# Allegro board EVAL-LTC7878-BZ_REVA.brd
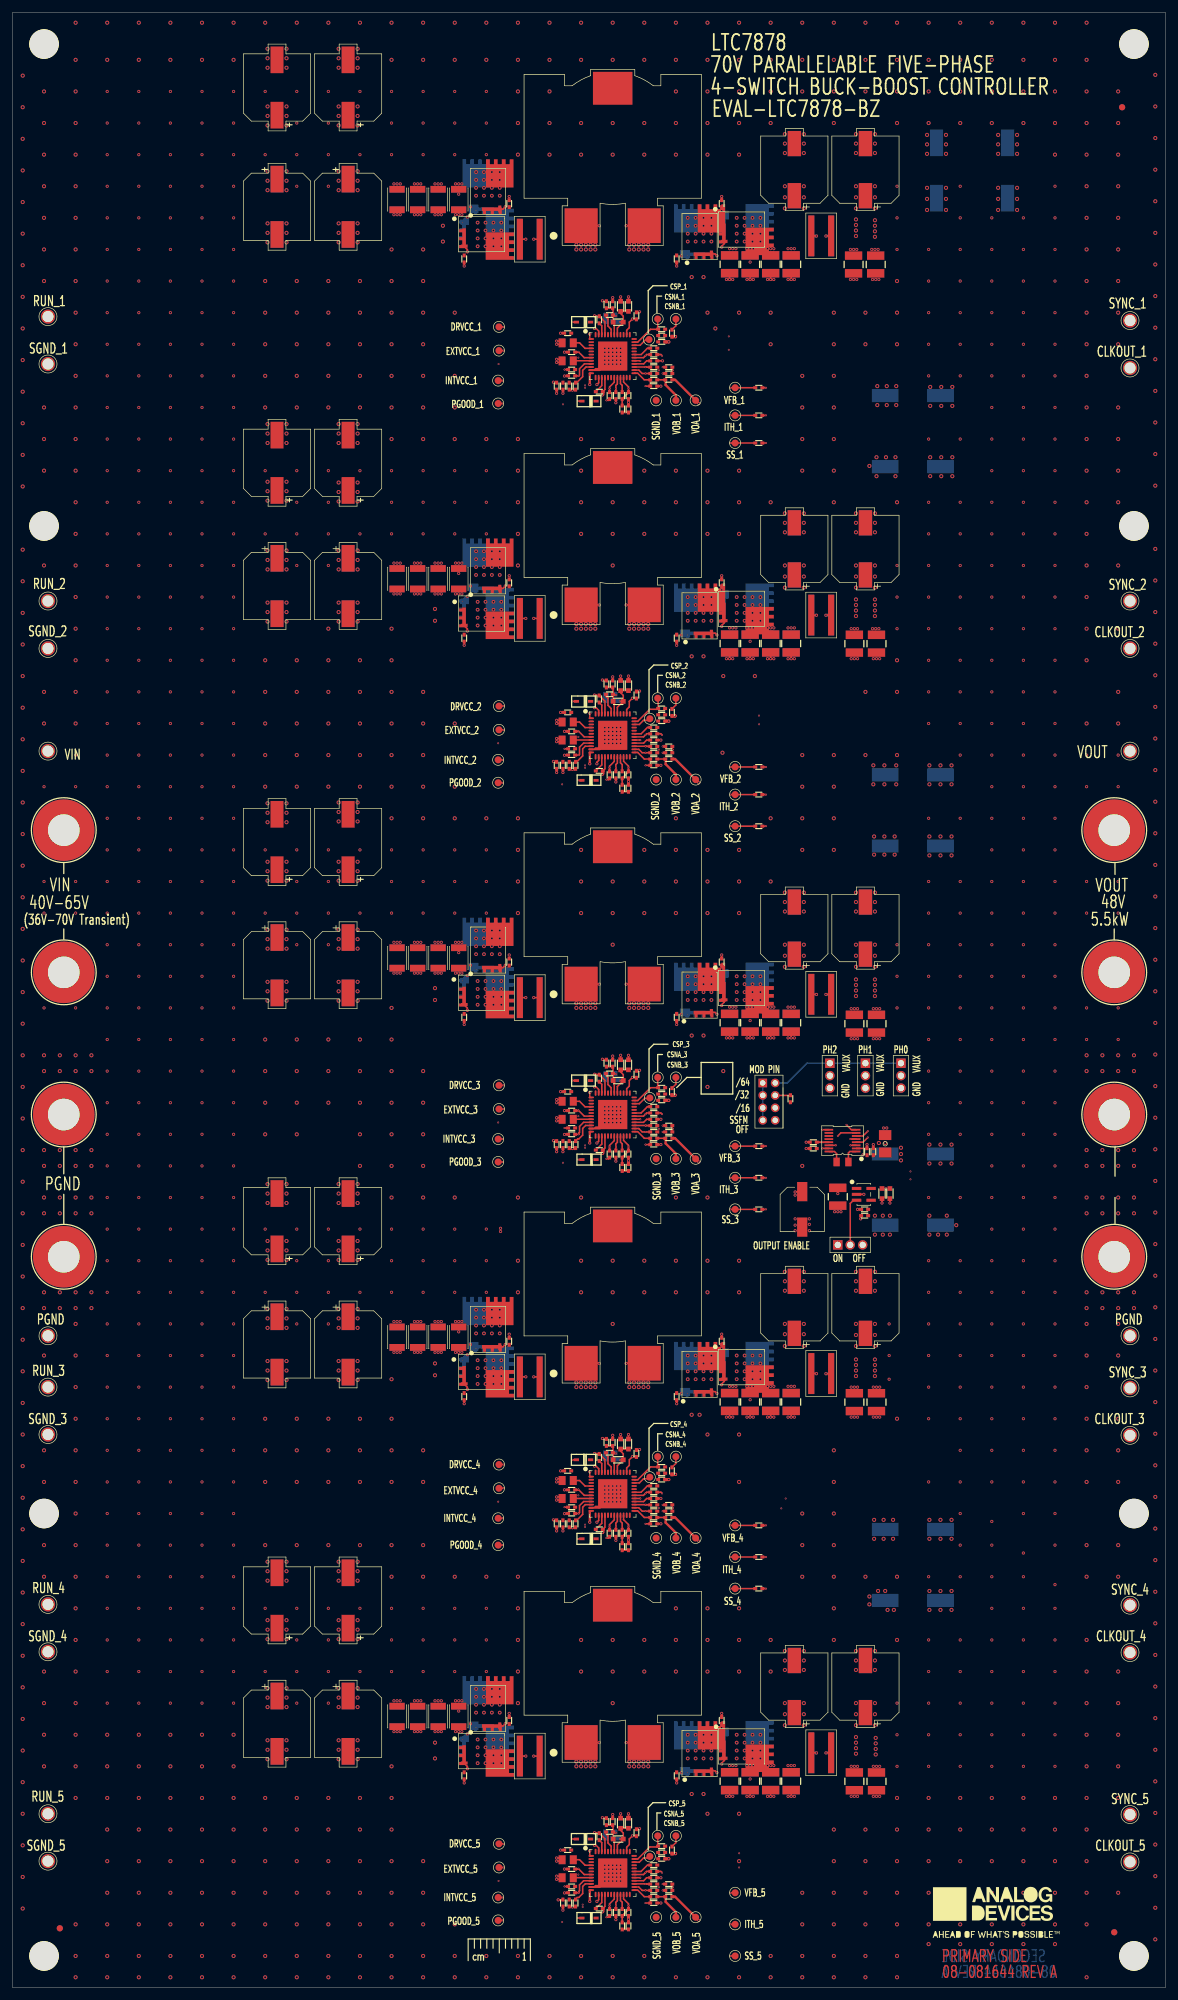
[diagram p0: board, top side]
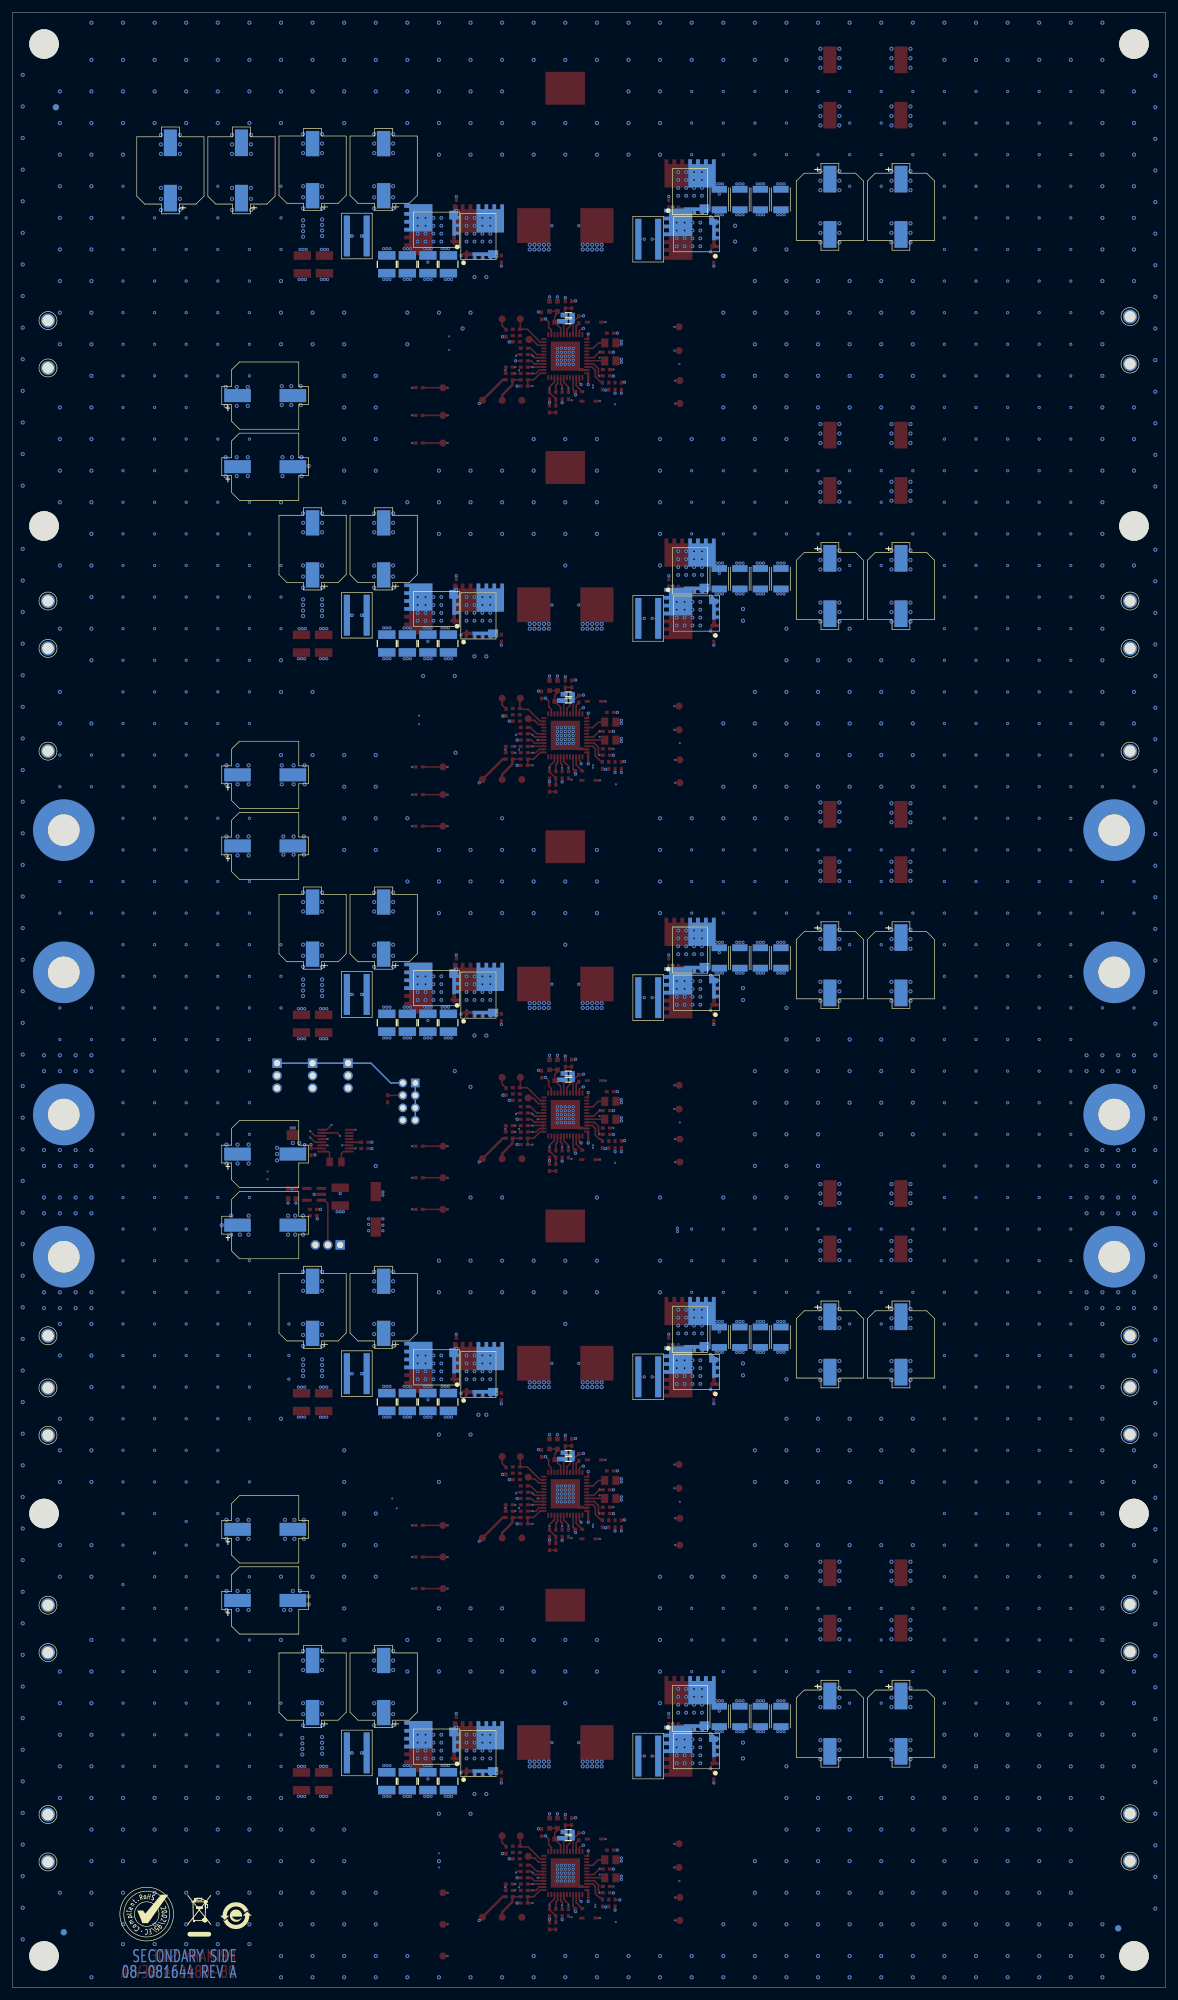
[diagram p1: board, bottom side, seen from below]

Outline 185.42 x 317.5 mm; copper layers: TOP, LAYER_2, LAYER_3, LAYER_4, LAYER_5, LAYER_6, LAYER_7, BOTTOM. Coordinates in mm from the lower left corner of the outline.
Outline path: 0,317.5 0,0 185.42,0 185.42,317.5 0,317.5

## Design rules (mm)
constraint set DEFAULT: min track width 0.254

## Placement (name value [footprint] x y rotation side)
C1  33uF  [CPLSMSQ406H413]  42.55 286.26 270 top
C2  33uF  [CPLSMSQ406H413]  53.98 286.26 270 top
C3  4.7uF  [C1210H87]  61.85 287.43 270 top
C4  4.7uF  [C1210H87]  61.85 287.43 270 bottom
C5  4.7uF  [C1210H87]  65.15 287.43 270 top
C6  4.7uF  [C1210H87]  65.15 287.43 270 bottom
C7  4.7uF  [C1210H87]  68.45 287.43 270 top
C8  4.7uF  [C1210H87]  68.45 287.43 270 bottom
C9  4.7uF  [C1210H87]  71.75 287.43 270 top
C10  4.7uF  [C1210H87]  71.75 287.43 270 bottom
C11  0.1UF  [C0402]  97.03 255.91 270 top
C12  1UF  [C0805H55]  89.28 264.39 180 top
C13  TBD0402  [C0402]  90.55 257.43 270 top
C14  100PF  [C0402]  99.06 255.91 270 top
C15  0.01uF  [C0402]  99.06 253.75 90 top
C16  1uF  [C0402]  94.36 268.1 90 top
C17  TBD0402  [C0402]  96.01 268.86 0 top
C18  6800pF  [C0603]  97.41 267.72 0 top
C19  1uF  [C0402]  94.36 256.54 180 top
C20  1UF  [C0805H55]  89.28 261.49 180 top
C21  4.7uF  [C0402]  89.92 259.08 180 top
C22  TBD0402  [C0402]  104.39 265.56 0 top
C23  4.7uF  [C0402]  89.92 262.89 180 top
C24  10UF  [C1210H110]  115.32 277.01 270 bottom
C25  10UF  [C1210H110]  118.62 277.01 270 bottom
C26  10UF  [C1210H110]  121.92 277.01 270 bottom
C27  10UF  [C1210H110]  125.22 277.01 270 top
C28  10UF  [C1210H110]  115.32 277.01 270 top
C29  10UF  [C1210H110]  118.62 277.01 270 top
C30  10UF  [C1210H110]  121.92 277.01 270 top
C31  10UF  [C1210H110]  125.22 277.01 270 bottom
C32  47UF  [CPLSMSQ406H433]  137.16 292.23 90 top
C33  47UF  [CPLSMSQ406H433]  125.73 292.23 90 top
C34  33uF  [CPLSMSQ406H413]  42.55 225.3 270 top
C35  33uF  [CPLSMSQ406H413]  53.98 225.3 270 top
C36  4.7uF  [C1210H87]  61.85 226.47 270 top
C37  4.7uF  [C1210H87]  61.85 226.47 270 bottom
C38  4.7uF  [C1210H87]  65.15 226.47 270 top
C39  4.7uF  [C1210H87]  65.15 226.47 270 bottom
C40  4.7uF  [C1210H87]  68.45 226.47 270 top
C41  4.7uF  [C1210H87]  68.45 226.47 270 bottom
C42  4.7uF  [C1210H87]  71.75 226.47 270 top
C43  4.7uF  [C1210H87]  71.75 226.47 270 bottom
C44  0.1UF  [C0402]  97.03 194.94 270 top
C45  1UF  [C0805H55]  89.28 203.43 180 top
C46  TBD0402  [C0402]  90.55 196.47 270 top
C47  100PF  [C0402]  99.06 194.94 270 top
C48  0.01uF  [C0402]  99.06 192.79 90 top
C49  1uF  [C0402]  94.36 207.14 90 top
C50  TBD0402  [C0402]  96.01 207.9 0 top
C51  6800pF  [C0603]  97.41 206.76 0 top
C52  1uF  [C0402]  94.36 195.58 180 top
C53  1UF  [C0805H55]  89.28 200.53 180 top
C54  4.7uF  [C0402]  89.92 198.12 180 top
C55  TBD0402  [C0402]  104.39 204.6 0 top
C56  4.7uF  [C0402]  89.92 201.93 180 top
C57  10UF  [C1210H110]  125.22 216.05 270 top
C58  10UF  [C1210H110]  118.62 216.05 270 top
C59  10UF  [C1210H110]  125.22 216.05 270 bottom
C60  10UF  [C1210H110]  121.92 216.05 270 top
C61  10UF  [C1210H110]  118.62 216.05 270 bottom
C62  10UF  [C1210H110]  121.92 216.05 270 bottom
C63  10UF  [C1210H110]  115.32 216.05 270 top
C64  10UF  [C1210H110]  115.32 216.05 270 bottom
C65  47UF  [CPLSMSQ406H433]  137.16 231.27 90 top
C66  47UF  [CPLSMSQ406H433]  125.73 231.27 90 top
C67  33uF  [CPLSMSQ406H413]  42.55 164.34 270 top
C68  33uF  [CPLSMSQ406H413]  53.98 164.34 270 top
C69  4.7uF  [C1210H87]  61.85 165.51 270 top
C70  4.7uF  [C1210H87]  61.85 165.51 270 bottom
C71  4.7uF  [C1210H87]  65.15 165.51 270 top
C72  4.7uF  [C1210H87]  65.15 165.51 270 bottom
C73  4.7uF  [C1210H87]  68.45 165.51 270 top
C74  4.7uF  [C1210H87]  68.45 165.51 270 bottom
C75  4.7uF  [C1210H87]  71.75 165.51 270 top
C76  4.7uF  [C1210H87]  71.75 165.51 270 bottom
C77  0.1UF  [C0402]  97.03 133.99 270 top
C78  1UF  [C0805H55]  89.28 142.47 180 top
C79  TBD0402  [C0402]  90.55 135.51 270 top
C80  100PF  [C0402]  99.06 133.99 270 top
C81  0.01uF  [C0402]  99.06 131.83 90 top
C82  1uF  [C0402]  94.36 146.18 90 top
C83  TBD0402  [C0402]  96.01 146.94 0 top
C84  6800pF  [C0603]  97.41 145.8 0 top
C85  1uF  [C0402]  94.36 134.62 180 top
C86  1UF  [C0805H55]  89.28 139.57 180 top
C87  4.7uF  [C0402]  89.92 137.16 180 top
C88  TBD0402  [C0402]  104.39 143.64 0 top
C89  4.7uF  [C0402]  89.92 140.97 180 top
C90  10UF  [C1210H110]  125.22 155.09 270 bottom
C91  10UF  [C1210H110]  125.22 155.09 270 top
C92  10UF  [C1210H110]  121.92 155.09 270 bottom
C93  10UF  [C1210H110]  118.62 155.09 270 bottom
C94  10UF  [C1210H110]  121.92 155.09 270 top
C95  10UF  [C1210H110]  118.62 155.09 270 top
C96  10UF  [C1210H110]  115.32 155.09 270 bottom
C97  10UF  [C1210H110]  115.32 155.09 270 top
C98  47UF  [CPLSMSQ406H433]  137.16 170.31 90 top
C99  47UF  [CPLSMSQ406H433]  125.73 170.31 90 top
C100  33uF  [CPLSMSQ406H413]  42.55 103.38 270 top
C101  33uF  [CPLSMSQ406H413]  53.98 103.38 270 top
C102  4.7uF  [C1210H87]  61.85 104.55 270 top
C103  4.7uF  [C1210H87]  61.85 104.55 270 bottom
C104  4.7uF  [C1210H87]  65.15 104.55 270 top
C105  4.7uF  [C1210H87]  65.15 104.55 270 bottom
C106  4.7uF  [C1210H87]  68.45 104.55 270 top
C107  4.7uF  [C1210H87]  68.45 104.55 270 bottom
C108  4.7uF  [C1210H87]  71.75 104.55 270 top
C109  4.7uF  [C1210H87]  71.75 104.55 270 bottom
C110  0.1UF  [C0402]  97.03 73.03 270 top
C111  1UF  [C0805H55]  89.28 81.51 180 top
C112  TBD0402  [C0402]  90.55 74.55 270 top
C113  100PF  [C0402]  99.06 73.03 270 top
C114  0.01uF  [C0402]  99.06 70.87 90 top
C115  1uF  [C0402]  94.36 85.22 90 top
C116  TBD0402  [C0402]  96.01 85.98 0 top
C117  6800pF  [C0603]  97.41 84.84 0 top
C118  1uF  [C0402]  94.36 73.66 180 top
C119  1UF  [C0805H55]  89.28 78.61 180 top
C120  4.7uF  [C0402]  89.92 76.2 180 top
C121  TBD0402  [C0402]  104.39 82.68 0 top
C122  4.7uF  [C0402]  89.92 80.01 180 top
C123  10UF  [C1210H110]  125.22 94.13 270 bottom
C124  10UF  [C1210H110]  125.22 94.13 270 top
C125  10UF  [C1210H110]  121.92 94.13 270 bottom
C126  10UF  [C1210H110]  118.62 94.13 270 bottom
C127  10UF  [C1210H110]  121.92 94.13 270 top
C128  10UF  [C1210H110]  118.62 94.13 270 top
C129  10UF  [C1210H110]  115.32 94.13 270 bottom
C130  10UF  [C1210H110]  115.32 94.13 270 top
C131  47UF  [CPLSMSQ406H433]  137.16 109.35 90 top
C132  47UF  [CPLSMSQ406H433]  125.73 109.35 90 top
C133  33uF  [CPLSMSQ406H413]  42.55 42.42 270 top
C134  33uF  [CPLSMSQ406H413]  53.98 42.42 270 top
C135  4.7uF  [C1210H87]  61.85 43.59 270 top
C136  4.7uF  [C1210H87]  61.85 43.59 270 bottom
C137  4.7uF  [C1210H87]  65.15 43.59 270 top
C138  4.7uF  [C1210H87]  65.15 43.59 270 bottom
C139  4.7uF  [C1210H87]  68.45 43.59 270 top
C140  4.7uF  [C1210H87]  68.45 43.59 270 bottom
C141  4.7uF  [C1210H87]  71.75 43.59 270 top
C142  4.7uF  [C1210H87]  71.75 43.59 270 bottom
C143  0.1UF  [C0402]  97.03 12.06 270 top
C144  1UF  [C0805H55]  89.28 20.55 180 top
C145  TBD0402  [C0402]  90.55 13.59 270 top
C146  100PF  [C0402]  99.06 12.06 270 top
C147  0.01uF  [C0402]  99.06 9.91 90 top
C148  1uF  [C0402]  94.36 24.26 90 top
C149  TBD0402  [C0402]  96.01 25.02 0 top
C150  6800pF  [C0603]  97.41 23.88 0 top
C151  1uF  [C0402]  94.36 12.7 180 top
C152  1UF  [C0805H55]  89.28 17.65 180 top
C153  4.7uF  [C0402]  89.92 15.24 180 top
C154  TBD0402  [C0402]  104.39 21.72 0 top
C155  4.7uF  [C0402]  89.92 19.05 180 top
C156  10UF  [C1210H110]  125.22 33.17 270 bottom
C157  10UF  [C1210H110]  125.22 33.17 270 top
C158  10UF  [C1210H110]  121.92 33.17 270 bottom
C159  10UF  [C1210H110]  118.62 33.17 270 bottom
C160  10UF  [C1210H110]  121.92 33.17 270 top
C161  10UF  [C1210H110]  118.62 33.17 270 top
C162  10UF  [C1210H110]  115.32 33.17 270 bottom
C163  10UF  [C1210H110]  115.32 33.17 270 top
C164  47UF  [CPLSMSQ406H433]  137.16 48.39 90 top
C165  47UF  [CPLSMSQ406H433]  125.73 48.39 90 top
C166  10UF  [CPLSMSQ260H315]  127 125.09 270 top
C167  1UF  [C1210H110]  132.72 127.13 270 top
C168  10UF  [C1206H71]  140.34 135.64 270 top
C169  0.1uF  [C0402]  138.43 134.37 270 top
C170  0.1uF  [C0402]  137.41 134.37 270 top
C171  0.47UF  [C0603]  139.83 127.64 270 top
C172  0.47UF  [C0603]  141.1 127.64 270 top
C173  0.1uF  [C0402]  128.78 135.89 180 top
C174  0.1uF  [C0402]  128.78 134.87 180 top
C175  1000pF  [C0402]  125.09 142.88 270 top
C176  33uF  [CPLSMSQ406H413]  42.55 286.26 270 bottom
C177  33uF  [CPLSMSQ406H413]  53.98 286.26 270 bottom
C178  47UF  [CPLSMSQ406H433]  137.16 292.23 90 bottom
C179  47UF  [CPLSMSQ406H433]  125.73 292.23 90 bottom
C180  33uF  [CPLSMSQ406H413]  42.55 225.3 270 bottom
C181  33uF  [CPLSMSQ406H413]  53.98 225.3 270 bottom
C182  47UF  [CPLSMSQ406H433]  137.16 231.27 90 bottom
C183  47UF  [CPLSMSQ406H433]  125.73 231.27 90 bottom
C184  33uF  [CPLSMSQ406H413]  42.55 164.34 270 bottom
C185  33uF  [CPLSMSQ406H413]  53.98 164.34 270 bottom
C186  47UF  [CPLSMSQ406H433]  137.16 170.31 90 bottom
C187  47UF  [CPLSMSQ406H433]  125.73 170.31 90 bottom
C188  33uF  [CPLSMSQ406H413]  42.55 103.38 270 bottom
C189  33uF  [CPLSMSQ406H413]  53.98 103.38 270 bottom
C190  47UF  [CPLSMSQ406H433]  137.16 109.35 90 bottom
C191  47UF  [CPLSMSQ406H433]  125.73 109.35 90 bottom
C192  33uF  [CPLSMSQ406H413]  42.55 42.42 270 bottom
C193  33uF  [CPLSMSQ406H413]  53.98 42.42 270 bottom
C194  47UF  [CPLSMSQ406H433]  137.16 48.39 90 bottom
C195  47UF  [CPLSMSQ406H433]  125.73 48.39 90 bottom
C196  10UF  [C1210H110]  135.25 276.99 270 top
C197  10UF  [C1210H110]  138.81 276.99 270 top
C198  10UF  [C1210H110]  138.94 216.03 270 top
C199  10UF  [C1210H110]  135.38 216.03 270 top
C200  10UF  [C1210H110]  135.38 154.94 270 top
C201  10UF  [C1210H110]  138.94 154.94 270 top
C202  10UF  [C1210H110]  135.38 94.11 270 top
C203  10UF  [C1210H110]  138.94 94.11 270 top
C204  10UF  [C1210H110]  135.38 33.15 270 top
C205  10UF  [C1210H110]  138.94 33.15 270 top
C206  33uF  [CPLSMSQ406H413]  42.55 305.44 90 top
C207  33uF  [CPLSMSQ406H413]  53.98 305.44 90 top
C208  33uF  [CPLSMSQ406H413]  148.59 292.1 90 bottom
C209  33uF  [CPLSMSQ406H413]  160.02 292.1 90 bottom
C210  33uF  [CPLSMSQ406H413]  42.55 245.11 90 top
C211  33uF  [CPLSMSQ406H413]  53.98 245.11 90 top
C212  33uF  [CPLSMSQ406H413]  144.78 244.47 180 bottom
C213  33uF  [CPLSMSQ406H413]  144.78 255.91 180 bottom
C214  33uF  [CPLSMSQ406H413]  42.55 184.15 90 top
C215  33uF  [CPLSMSQ406H413]  53.98 184.15 90 top
C216  33uF  [CPLSMSQ406H413]  144.78 183.51 180 bottom
C217  33uF  [CPLSMSQ406H413]  144.78 194.94 180 bottom
C218  33uF  [CPLSMSQ406H413]  42.55 123.19 90 top
C219  33uF  [CPLSMSQ406H413]  53.98 123.19 90 top
C220  33uF  [CPLSMSQ406H413]  144.78 133.99 180 bottom
C221  33uF  [CPLSMSQ406H413]  144.78 122.56 180 bottom
C222  33uF  [CPLSMSQ406H413]  42.55 62.23 90 top
C223  33uF  [CPLSMSQ406H413]  53.98 62.23 90 top
C224  33uF  [CPLSMSQ406H413]  144.78 62.23 180 bottom
C225  33uF  [CPLSMSQ406H413]  144.78 73.66 180 bottom
D1  BAT46WJ,115  [SOD323F]  91.82 267.72 180 top
D2  BAT46WJ,115  [SOD323F]  92.71 255.02 180 top
D3  BAT46WJ,115  [SOD323F]  91.82 206.76 180 top
D4  BAT46WJ,115  [SOD323F]  92.71 194.06 180 top
D5  BAT46WJ,115  [SOD323F]  91.82 145.8 180 top
D6  BAT46WJ,115  [SOD323F]  92.71 133.1 180 top
D7  BAT46WJ,115  [SOD323F]  91.82 84.84 180 top
D8  BAT46WJ,115  [SOD323F]  92.71 72.14 180 top
D9  BAT46WJ,115  [SOD323F]  91.82 23.88 180 top
D10  BAT46WJ,115  [SOD323F]  92.71 11.18 180 top
J1  CKFH1032-10  [CNCFCKFH1032-10]  8.26 163.19 0 top
J2  CKFH1032-10  [CNCFCKFH1032-10]  8.26 140.34 0 top
J3  CKFH1032-10  [CNCFCKFH1032-10]  177.16 163.19 0 top
J4  CKFH1032-10  [CNCFCKFH1032-10]  177.16 140.34 0 top
J5  CKFH1032-10  [CNCFCKFH1032-10]  8.26 186.06 0 top
J6  CKFH1032-10  [CNCFCKFH1032-10]  8.26 117.47 0 top
J7  CKFH1032-10  [CNCFCKFH1032-10]  177.16 186.06 0 top
J8  CKFH1032-10  [CNCFCKFH1032-10]  177.16 117.47 0 top
JP1  TMM-103-02-L-S  [CNTHMHDR1X3L236W78H215]  142.88 148.59 270 top
JP2  TMM-103-02-L-S  [CNTHMHDR1X3L236W78H215]  137.16 148.59 270 top
JP3  TMM-103-02-L-S  [CNTHMHDR1X3L236W78H215]  131.44 148.59 270 top
JP4  TMM-103-02-L-S  [CNTHMHDR1X3L236W78H215]  132.72 119.38 0 top
JP5  62000821121  [CNTHMHDR2X4L315W157H248]  120.65 145.41 270 top
L1  10UH  [LSML1102W764H728]  96.52 294.79 0 top
L2  10UH  [LSML1102W764H728]  96.52 233.83 0 top
L3  10UH  [LSML1102W764H728]  96.52 172.87 0 top
L4  10UH  [LSML1102W764H728]  96.52 111.91 0 top
L5  10UH  [LSML1102W764H728]  96.52 50.95 0 top
M1  ISC022N10NM6ATMA1  [SON8_FL]  76.45 288.7 0 top
M2  ISC022N10NM6ATMA1  [SON8_FL]  75.44 281.84 270 top
M3  ISC022N10NM6ATMA1  [SON8_FL]  110.49 281.46 0 top
M4  ISC022N10NM6ATMA1  [SON8_FL]  117.22 282.6 270 top
M5  ISC022N10NM6ATMA1  [SON8_FL]  76.45 288.7 180 bottom
M6  ISC022N10NM6ATMA1  [SON8_FL]  75.44 281.84 90 bottom
M7  ISC022N10NM6ATMA1  [SON8_FL]  110.49 281.46 180 bottom
M8  ISC022N10NM6ATMA1  [SON8_FL]  117.22 282.57 90 bottom
M9  ISC022N10NM6ATMA1  [SON8_FL]  76.45 227.74 0 top
M10  ISC022N10NM6ATMA1  [SON8_FL]  75.44 220.88 270 top
M11  ISC022N10NM6ATMA1  [SON8_FL]  110.49 220.5 0 top
M12  ISC022N10NM6ATMA1  [SON8_FL]  117.22 221.64 270 top
M13  ISC022N10NM6ATMA1  [SON8_FL]  76.45 227.74 180 bottom
M14  ISC022N10NM6ATMA1  [SON8_FL]  75.44 220.88 90 bottom
M15  ISC022N10NM6ATMA1  [SON8_FL]  110.49 220.5 180 bottom
M16  ISC022N10NM6ATMA1  [SON8_FL]  117.22 221.62 90 bottom
M17  ISC022N10NM6ATMA1  [SON8_FL]  76.45 166.78 0 top
M18  ISC022N10NM6ATMA1  [SON8_FL]  75.44 159.92 270 top
M19  ISC022N10NM6ATMA1  [SON8_FL]  110.49 159.54 0 top
M20  ISC022N10NM6ATMA1  [SON8_FL]  117.22 160.68 270 top
M21  ISC022N10NM6ATMA1  [SON8_FL]  76.45 166.78 180 bottom
M22  ISC022N10NM6ATMA1  [SON8_FL]  75.44 159.92 90 bottom
M23  ISC022N10NM6ATMA1  [SON8_FL]  110.49 159.54 180 bottom
M24  ISC022N10NM6ATMA1  [SON8_FL]  117.22 160.66 90 bottom
M25  ISC022N10NM6ATMA1  [SON8_FL]  76.45 105.82 0 top
M26  ISC022N10NM6ATMA1  [SON8_FL]  75.44 98.96 270 top
M27  ISC022N10NM6ATMA1  [SON8_FL]  110.49 98.58 0 top
M28  ISC022N10NM6ATMA1  [SON8_FL]  117.22 99.72 270 top
M29  ISC022N10NM6ATMA1  [SON8_FL]  76.45 105.82 180 bottom
M30  ISC022N10NM6ATMA1  [SON8_FL]  75.44 98.96 90 bottom
M31  ISC022N10NM6ATMA1  [SON8_FL]  110.49 98.58 180 bottom
M32  ISC022N10NM6ATMA1  [SON8_FL]  117.22 99.69 90 bottom
M33  ISC022N10NM6ATMA1  [SON8_FL]  76.45 44.86 0 top
M34  ISC022N10NM6ATMA1  [SON8_FL]  75.44 38 270 top
M35  ISC022N10NM6ATMA1  [SON8_FL]  110.49 37.62 0 top
M36  ISC022N10NM6ATMA1  [SON8_FL]  117.22 38.76 270 top
M37  ISC022N10NM6ATMA1  [SON8_FL]  76.45 44.86 180 bottom
M38  ISC022N10NM6ATMA1  [SON8_FL]  75.44 38 90 bottom
M39  ISC022N10NM6ATMA1  [SON8_FL]  110.49 37.62 180 bottom
M40  ISC022N10NM6ATMA1  [SON8_FL]  117.22 38.73 90 bottom
NOREF  -  []  20.32 12.7 0 top
NOREF#2  -  []  -201.93 -133.35 0 top
NOREF#3  -  [unnamed#2]  180.34 312.42 180 top
NOREF#4  -  []  20.32 76.2 270 top
NOREF#5  -  []  -55.88 -63.5 0 top
NOREF#6  -  []  -55.88 -63.5 0 top
NOREF#7  -  [unnamed#2]  178.44 302.26 0 top
NOREF#8  -  [unnamed#2]  7.62 9.53 0 top
NOREF#9  -  [unnamed#2]  180.34 76.2 180 top
NOREF#10  -  []  83.82 76.2 180 top
NOREF#11  -  []  264.67 298.7 0 top
NOREF#12  -  []  328.68 169.16 0 top
NOREF#13  -  []  269.37 264.8 0 top
NOREF#14  -  [unnamed#2]  180.34 234.95 180 top
NOREF#15  -  [unnamed#2]  5.08 5.08 180 top
NOREF#16  -  [unnamed#2]  5.08 76.2 180 top
NOREF#17  -  [unnamed#2]  177.16 8.89 0 top
NOREF#18  -  []  73.28 4.32 0 top
NOREF#19  -  [unnamed#2]  5.08 312.42 180 top
NOREF#20  -  []  309.75 227.71 0 top
NOREF#21  -  []  185.42 0 90 top
NOREF#22  -  [unnamed#2]  5.08 234.95 180 top
NOREF#23  -  []  254 50.8 0 top
NOREF#24  -  [unnamed#2]  180.34 5.08 180 top
NOREF#25  -  []  97.16 324.49 0 top
NOREF#26  -  []  -55.88 -63.5 0 top
NOREF#27  -  []  83.82 12.7 90 top
NOREF#28  -  []  157.61 12.06 0 top
NOREF#29  -  []  160.66 5.71 270 top
NOREF#30  -  []  -201.93 -133.35 0 top
NOREF#31  -  []  0 317.5 0 top
NOREF#32  -  [unnamed#2]  178.44 302.26 180 bottom
NOREF#33  -  []  149.48 11.56 180 bottom
NOREF#34  -  []  163.83 11.81 180 bottom
NOREF#35  -  [unnamed#2]  7.62 9.53 180 bottom
NOREF#36  -  []  155.57 8.26 180 bottom
NOREF#37  -  [unnamed#2]  177.16 8.89 180 bottom
R1  0  [R0402]  103.12 262.51 180 top
R2  0  [R0402]  87.5 257.43 270 top
R3  0  [R0402]  120.02 248.28 0 top
R4  0  [R0402]  120.02 252.73 0 top
R5  0  [R0402]  120.02 257.18 0 top
R6  1  [R0402]  89.28 204.98 0 top
R7  301K  [R0402]  88.52 257.43 90 top
R8  10.7K  [R0402]  89.53 257.43 90 top
R9  0  [R0402]  79.88 286.77 90 top
R10  0  [R0402]  72.64 277.88 270 top
R11  0  [R0402]  98.04 255.91 90 top
R12  10K  [R0402]  98.04 253.75 270 top
R13  0  [R0402]  95.5 270.51 270 top
R14  0.003  [R1225H28]  83.19 281.05 0 top
R15  0.003  [R1225H28]  83.19 281.05 0 bottom
R16  49.9  [R0603]  97.79 270.26 270 top
R17  0  [R0402]  96.01 268.86 0 bottom
R18  69.8K  [R0402]  103.12 261.49 0 top
R19  TBD0402  [R0402]  96.52 270.51 270 top
R20  TBD0402  [R0402]  103.12 263.52 0 top
R21  TBD0402  [R0402]  96.01 267.84 0 bottom
R22  0  [R0402]  103.12 259.46 0 top
R23  TBD0603  [R0603]  99.06 270.26 270 top
R24  0  [R0402]  103.12 260.48 0 top
R25  TBD0402  [R0402]  105.54 260.48 0 top
R26  TBD0402  [R0402]  105.54 259.46 0 top
R27  100K  [R0402]  96.01 255.91 270 top
R28  0  [R0402]  106.81 277.88 270 top
R29  0  [R0402]  104.39 266.57 0 top
R30  0  [R0402]  114.05 286.77 90 top
R31  0  [R0402]  104.39 264.54 0 top
R32  0  [R0402]  106.05 265.94 270 top
R33  0  [R1225H28]  130.05 281.59 0 top
R34  0  [R0402]  105.54 258.44 180 top
R35  475K  [R0402]  103.12 258.44 180 top
R36  10K  [R0402]  103.12 257.43 0 top
R37  301K  [R0402]  88.52 196.47 90 top
R38  10.7K  [R0402]  89.53 196.47 90 top
R39  0  [R0402]  79.88 225.81 90 top
R40  0  [R0402]  72.64 216.92 270 top
R41  0  [R0402]  98.04 194.94 90 top
R42  10K  [R0402]  98.04 192.79 270 top
R43  0  [R0402]  95.5 209.55 270 top
R44  0.003  [R1225H28]  83.19 220.09 0 top
R45  0.003  [R1225H28]  83.19 220.09 0 bottom
R46  49.9  [R0603]  97.79 209.3 270 top
R47  0  [R0402]  96.01 207.9 0 bottom
R48  69.8K  [R0402]  103.12 200.53 0 top
R49  TBD0402  [R0402]  96.52 209.55 270 top
R50  TBD0402  [R0402]  103.12 202.56 0 top
R51  TBD0402  [R0402]  96.01 206.88 0 bottom
R52  0  [R0402]  103.12 198.5 0 top
R53  TBD0603  [R0603]  99.06 209.3 270 top
R54  0  [R0402]  103.12 199.52 0 top
R55  TBD0402  [R0402]  105.54 199.52 0 top
R56  TBD0402  [R0402]  105.54 198.5 0 top
R57  100K  [R0402]  96.01 194.94 270 top
R58  0  [R0402]  106.81 216.92 270 top
R59  0  [R0402]  104.39 205.61 0 top
R60  0  [R0402]  114.05 225.81 90 top
R61  0  [R0402]  104.39 203.58 0 top
R62  0  [R0402]  106.05 204.98 270 top
R63  0  [R1225H28]  130.05 220.63 0 top
R64  0  [R0402]  105.54 197.49 180 top
R65  475K  [R0402]  103.12 197.49 180 top
R66  10K  [R0402]  103.12 196.47 0 top
R67  1  [R0402]  89.92 199.14 180 top
R68  5.1  [R0402]  100.33 207.77 90 top
R69  1  [R0402]  89.28 265.94 0 top
R70  1  [R0402]  89.92 260.1 180 top
R71  5.1  [R0402]  100.33 268.73 90 top
R72  301K  [R0402]  88.52 135.51 90 top
R73  1  [R0402]  89.28 144.02 0 top
R74  10.7K  [R0402]  89.53 135.51 90 top
R75  0  [R0402]  79.88 164.85 90 top
R76  0  [R0402]  72.64 155.96 270 top
R77  0  [R0402]  98.04 133.99 90 top
R78  10K  [R0402]  98.04 131.83 270 top
R79  0  [R0402]  95.5 148.59 270 top
R80  0.003  [R1225H28]  83.19 159.13 0 top
R81  0.003  [R1225H28]  83.19 159.13 0 bottom
R82  49.9  [R0603]  97.79 148.34 270 top
R83  0  [R0402]  96.01 146.94 0 bottom
R84  69.8K  [R0402]  103.12 139.57 0 top
R85  TBD0402  [R0402]  96.52 148.59 270 top
R86  TBD0402  [R0402]  103.12 141.6 0 top
R87  TBD0402  [R0402]  96.01 145.92 0 bottom
R88  0  [R0402]  103.12 137.54 0 top
R89  TBD0603  [R0603]  99.06 148.34 270 top
R90  0  [R0402]  103.12 138.56 0 top
R91  TBD0402  [R0402]  105.54 138.56 0 top
R92  TBD0402  [R0402]  105.54 137.54 0 top
R93  100K  [R0402]  96.01 133.99 270 top
R94  1  [R0402]  89.92 138.18 180 top
R95  0  [R0402]  106.81 155.96 270 top
R96  0  [R0402]  104.39 144.65 0 top
R97  0  [R0402]  114.05 164.85 90 top
R98  5.1  [R0402]  100.33 146.81 90 top
R99  0  [R0402]  104.39 142.62 0 top
R100  0  [R0402]  106.05 144.02 270 top
R101  0  [R1225H28]  130.05 159.67 0 top
R102  0  [R0402]  105.54 136.53 180 top
R103  475K  [R0402]  103.12 136.53 180 top
R104  10K  [R0402]  103.12 135.51 0 top
R105  301K  [R0402]  88.52 74.55 90 top
R106  1  [R0402]  89.28 83.06 0 top
R107  10.7K  [R0402]  89.53 74.55 90 top
R108  0  [R0402]  79.88 103.89 90 top
R109  0  [R0402]  72.64 95 270 top
R110  0  [R0402]  98.04 73.03 90 top
R111  10K  [R0402]  98.04 70.87 270 top
R112  0  [R0402]  95.5 87.63 270 top
R113  0.003  [R1225H28]  83.19 98.17 0 top
R114  0.003  [R1225H28]  83.19 98.17 0 bottom
R115  49.9  [R0603]  97.79 87.38 270 top
R116  0  [R0402]  96.01 85.98 0 bottom
R117  69.8K  [R0402]  103.12 78.61 0 top
R118  TBD0402  [R0402]  96.52 87.63 270 top
R119  TBD0402  [R0402]  103.12 80.64 0 top
R120  TBD0402  [R0402]  96.01 84.96 0 bottom
R121  0  [R0402]  103.12 76.58 0 top
R122  TBD0603  [R0603]  99.06 87.38 270 top
R123  0  [R0402]  103.12 77.6 0 top
R124  TBD0402  [R0402]  105.54 77.6 0 top
R125  TBD0402  [R0402]  105.54 76.58 0 top
R126  100K  [R0402]  96.01 73.03 270 top
R127  1  [R0402]  89.92 77.22 180 top
R128  0  [R0402]  106.81 95 270 top
R129  0  [R0402]  104.39 83.69 0 top
R130  0  [R0402]  114.05 103.89 90 top
R131  5.1  [R0402]  100.33 85.85 90 top
R132  0  [R0402]  104.39 81.66 0 top
R133  0  [R0402]  106.05 83.06 270 top
R134  0  [R1225H28]  130.05 98.71 0 top
R135  0  [R0402]  105.54 75.56 180 top
R136  475K  [R0402]  103.12 75.56 180 top
R137  10K  [R0402]  103.12 74.55 0 top
R138  301K  [R0402]  88.52 13.59 90 top
R139  1  [R0402]  89.28 22.1 0 top
R140  10.7K  [R0402]  89.53 13.59 90 top
R141  0  [R0402]  79.88 42.93 90 top
R142  0  [R0402]  72.64 34.04 270 top
R143  0  [R0402]  98.04 12.06 90 top
R144  10K  [R0402]  98.04 9.91 270 top
R145  0  [R0402]  95.5 26.67 270 top
R146  0.003  [R1225H28]  83.19 37.21 0 top
R147  0.003  [R1225H28]  83.19 37.21 0 bottom
R148  49.9  [R0603]  97.79 26.42 270 top
R149  0  [R0402]  96.01 25.02 0 bottom
R150  69.8K  [R0402]  103.12 17.65 0 top
R151  TBD0402  [R0402]  96.52 26.67 270 top
R152  TBD0402  [R0402]  103.12 19.68 0 top
R153  TBD0402  [R0402]  96.01 24 0 bottom
R154  0  [R0402]  103.12 15.62 0 top
R155  TBD0603  [R0603]  99.06 26.42 270 top
R156  0  [R0402]  103.12 16.64 0 top
R157  TBD0402  [R0402]  105.54 16.64 0 top
R158  TBD0402  [R0402]  105.54 15.62 0 top
R159  100K  [R0402]  96.01 12.06 270 top
R160  1  [R0402]  89.92 16.26 180 top
R161  0  [R0402]  106.81 34.04 270 top
R162  0  [R0402]  104.39 22.73 0 top
R163  0  [R0402]  114.05 42.93 90 top
R164  5.1  [R0402]  100.33 24.89 90 top
R165  0  [R0402]  104.39 20.7 0 top
R166  0  [R0402]  106.05 22.1 270 top
R167  0  [R1225H28]  130.05 37.75 0 top
R168  0  [R0402]  105.54 14.61 180 top
R169  475K  [R0402]  103.12 14.61 180 top
R170  10K  [R0402]  103.12 13.59 0 top
R171  0  [R0402]  103.12 201.55 180 top
R172  0  [R0402]  87.5 196.47 270 top
R173  0  [R0402]  120.02 186.69 0 top
R174  0  [R0402]  120.02 191.77 0 top
R175  0  [R0402]  120.02 196.22 0 top
R176  0  [R0402]  103.12 140.59 180 top
R177  0  [R0402]  87.5 135.51 270 top
R178  0  [R0402]  120.02 125.09 0 top
R179  0  [R0402]  120.02 130.18 0 top
R180  0  [R0402]  120.02 135.25 0 top
R181  0  [R0402]  103.12 79.63 180 top
R182  0  [R0402]  87.5 74.55 270 top
R183  0  [R0402]  120.02 64.14 0 top
R184  0  [R0402]  120.02 69.22 0 top
R185  0  [R0402]  120.02 74.3 0 top
R186  0  [R0402]  103.12 18.67 180 top
R187  267K  [R0805]  133.48 132.72 180 top
R188  3.9MEG  [R0402]  137.03 124.08 0 top
R189  2.21M  [R0402]  137.03 125.09 180 top
R190  0  [R1225H28]  130.05 281.56 0 bottom
R191  0  [R1225H28]  130.05 220.6 0 bottom
R192  0  [R1225H28]  130.05 159.64 0 bottom
R193  0  [R1225H28]  130.05 98.68 0 bottom
R194  0  [R1225H28]  130.05 37.72 0 bottom
TP1  2308-2-00-80-00-00-07-0  [CNMILLMAX2308]  5.71 198.75 0 top
TP2  2308-2-00-80-00-00-07-0  [CNMILLMAX2308]  5.71 96.52 0 top
TP3  2308-2-00-80-00-00-07-0  [CNMILLMAX2308]  5.71 88.9 0 top
TP4  2308-2-00-80-00-00-07-0  [CNMILLMAX2308]  5.71 104.78 0 top
TP5  2308-2-00-80-00-00-07-0  [CNMILLMAX2308]  5.71 268.61 0 top
TP6  2308-2-00-80-00-00-07-0  [CNMILLMAX2308]  5.71 260.99 0 top
TP7  2308-2-00-80-00-00-07-0  [CNMILLMAX2308]  179.71 267.97 0 top
TP8  2308-2-00-80-00-00-07-0  [CNMILLMAX2308]  179.71 260.35 0 top
TP9  TESTPAD  [TPSMC40]  116.2 248.28 0 top
TP10  TESTPAD  [TPSMC40]  116.2 252.73 0 top
TP11  TESTPAD  [TPSMC40]  103.76 268.22 0 top
TP12  TESTPAD  [TPSMC40]  78.23 263.14 0 top
TP13  TESTPAD  [TPSMC40]  106.68 268.22 0 top
TP14  TESTPAD  [TPSMC40]  78.11 258.32 0 top
TP15  TESTPAD  [TPSMC40]  78.11 254.63 0 top
TP16  TESTPAD  [TPSMC40]  102.36 264.92 0 top
TP17  TESTPAD  [TPSMC40]  78.23 266.95 0 top
TP18  TESTPAD  [TPSMC40]  116.2 257.18 0 top
TP19  TESTPAD  [TPSMC40]  109.86 255.14 0 top
TP20  TESTPAD  [TPSMC40]  106.68 255.14 0 top
TP21  TESTPAD  [TPSMC40]  103.5 255.14 0 top
TP22  2308-2-00-80-00-00-07-0  [CNMILLMAX2308]  179.71 198.75 0 top
TP23  2308-2-00-80-00-00-07-0  [CNMILLMAX2308]  179.71 96.39 0 top
TP24  2308-2-00-80-00-00-07-0  [CNMILLMAX2308]  179.71 88.77 0 top
TP25  2308-2-00-80-00-00-07-0  [CNMILLMAX2308]  179.71 104.78 0 top
TP26  TESTPAD  [TPSMC40]  116.2 125.09 0 top
TP27  TESTPAD  [TPSMC40]  116.2 130.18 0 top
TP28  TESTPAD  [TPSMC40]  103.76 146.3 0 top
TP29  TESTPAD  [TPSMC40]  78.23 141.22 0 top
TP30  2308-2-00-80-00-00-07-0  [CNMILLMAX2308]  5.71 222.88 0 top
TP31  2308-2-00-80-00-00-07-0  [CNMILLMAX2308]  5.71 215.26 0 top
TP32  2308-2-00-80-00-00-07-0  [CNMILLMAX2308]  179.71 222.88 0 top
TP33  2308-2-00-80-00-00-07-0  [CNMILLMAX2308]  179.71 215.26 0 top
TP34  TESTPAD  [TPSMC40]  116.2 186.69 0 top
TP35  TESTPAD  [TPSMC40]  116.2 191.77 0 top
TP36  TESTPAD  [TPSMC40]  103.76 207.26 0 top
TP37  TESTPAD  [TPSMC40]  78.23 202.18 0 top
TP38  TESTPAD  [TPSMC40]  106.68 207.26 0 top
TP39  TESTPAD  [TPSMC40]  78.11 197.36 0 top
TP40  TESTPAD  [TPSMC40]  78.11 193.68 0 top
TP41  TESTPAD  [TPSMC40]  102.49 203.96 0 top
TP42  TESTPAD  [TPSMC40]  78.23 205.99 0 top
TP43  TESTPAD  [TPSMC40]  116.2 196.22 0 top
TP44  TESTPAD  [TPSMC40]  109.86 194.18 0 top
TP45  TESTPAD  [TPSMC40]  106.68 194.18 0 top
TP46  TESTPAD  [TPSMC40]  103.5 194.18 0 top
TP47  TESTPAD  [TPSMC40]  106.68 146.3 0 top
TP48  TESTPAD  [TPSMC40]  78.11 136.4 0 top
TP49  TESTPAD  [TPSMC40]  78.11 132.72 0 top
TP50  TESTPAD  [TPSMC40]  102.49 143 0 top
TP51  TESTPAD  [TPSMC40]  78.23 145.03 0 top
TP52  TESTPAD  [TPSMC40]  116.2 135.25 0 top
TP53  TESTPAD  [TPSMC40]  109.86 133.22 0 top
TP54  TESTPAD  [TPSMC40]  106.68 133.22 0 top
TP55  TESTPAD  [TPSMC40]  103.5 133.22 0 top
TP56  2308-2-00-80-00-00-07-0  [CNMILLMAX2308]  5.71 61.59 0 top
TP57  2308-2-00-80-00-00-07-0  [CNMILLMAX2308]  5.71 53.98 0 top
TP58  2308-2-00-80-00-00-07-0  [CNMILLMAX2308]  179.71 61.47 0 top
TP59  2308-2-00-80-00-00-07-0  [CNMILLMAX2308]  179.71 53.85 0 top
TP60  TESTPAD  [TPSMC40]  116.2 64.14 0 top
TP61  TESTPAD  [TPSMC40]  116.2 69.22 0 top
TP62  TESTPAD  [TPSMC40]  103.76 85.34 0 top
TP63  TESTPAD  [TPSMC40]  78.23 80.26 0 top
TP64  TESTPAD  [TPSMC40]  106.68 85.34 0 top
TP65  TESTPAD  [TPSMC40]  78.11 75.44 0 top
TP66  TESTPAD  [TPSMC40]  78.11 71.12 0 top
TP67  TESTPAD  [TPSMC40]  102.49 82.04 0 top
TP68  TESTPAD  [TPSMC40]  78.23 84.07 0 top
TP69  TESTPAD  [TPSMC40]  116.2 74.3 0 top
TP70  TESTPAD  [TPSMC40]  109.86 72.26 0 top
TP71  TESTPAD  [TPSMC40]  106.68 72.26 0 top
TP72  TESTPAD  [TPSMC40]  103.5 72.26 0 top
TP73  2308-2-00-80-00-00-07-0  [CNMILLMAX2308]  5.71 27.94 0 top
TP74  2308-2-00-80-00-00-07-0  [CNMILLMAX2308]  5.71 20.32 0 top
TP75  2308-2-00-80-00-00-07-0  [CNMILLMAX2308]  179.71 27.81 0 top
TP76  2308-2-00-80-00-00-07-0  [CNMILLMAX2308]  179.71 20.19 0 top
TP77  TESTPAD  [TPSMC40]  116.2 5.08 0 top
TP78  TESTPAD  [TPSMC40]  116.2 10.16 0 top
TP79  TESTPAD  [TPSMC40]  103.76 24.38 0 top
TP80  TESTPAD  [TPSMC40]  78.23 19.3 0 top
TP81  TESTPAD  [TPSMC40]  106.68 24.38 0 top
TP82  TESTPAD  [TPSMC40]  78.11 14.48 0 top
TP83  TESTPAD  [TPSMC40]  78.11 10.79 0 top
TP84  TESTPAD  [TPSMC40]  102.49 21.08 0 top
TP85  TESTPAD  [TPSMC40]  78.23 23.11 0 top
TP86  TESTPAD  [TPSMC40]  116.2 15.24 0 top
TP87  TESTPAD  [TPSMC40]  109.86 11.3 0 top
TP88  TESTPAD  [TPSMC40]  106.68 11.3 0 top
TP89  TESTPAD  [TPSMC40]  103.5 11.3 0 top
U1  LTC7878AUK#PBF  [QFN48_7X7_PAD4_7X4_7_A]  96.52 262.25 270 top
U2  LTC7878AUK#PBF  [QFN48_7X7_PAD4_7X4_7_A]  96.52 201.29 270 top
U3  LTC7878AUK#PBF  [QFN48_7X7_PAD4_7X4_7_A]  96.52 140.34 270 top
U4  LTC7878AUK#PBF  [QFN48_7X7_PAD4_7X4_7_A]  96.52 79.38 270 top
U5  LTC7878AUK#PBF  [QFN48_7X7_PAD4_7X4_7_A]  96.52 18.41 270 top
U6  LT3014ES5#TRPBF  [TSOT-5]  136.91 127.51 270 top
U7  LTC6909CMS#PBF  [MSOP16]  133.48 136.14 90 top

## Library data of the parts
C1 C2 C34 C35 C67 C68 C100 C101 C133 C134 C176 C177 C180 C181 C184 C185 C188 C189 C192 C193 C206-C225 = CAPP: User Part Number: UPN; Tolerance: 20; alternate symbols: (); part number: CAPP_SM-33UF,80V,20,E039984,CPLSMSQ406H413; tolerance: 20
C3-C10 C36-C43 C69-C76 C102-C109 C135-C142 = CAP: Tolerance: 10; User Part Number: UPN; alternate symbols: (); part number: CAP_SM-4.7UF,100V,10,E033812,C1210H87; tolerance: 10
C11 C44 C77 C110 C143 = CAP: Tolerance: 10; User Part Number: UPN; alternate symbols: (C0402L); part number: CAP_SM-0.1UF,10V,10,E042769,C0402; tolerance: 10
C12 C20 C45 C53 C78 C86 C111 C119 C144 C152 = CAP: User Part Number: UPN; Tolerance: 10; alternate symbols: (); part number: CAP_SM-1UF,100V,10,E048499,C0805H55; tolerance: 10
C13 C17 C22 C46 C50 C55 C79 C83 C88 C112 C116 C121 C145 C149 C154 = CAP: User Part Number: UPN; alternate symbols: (C0402L_ALT,C0402L); part number: CAP_SM-TBD0402,TBD0402,TBD0402,E000381,C0402
C14 C47 C80 C113 C146 = CAP: Tolerance: 20; User Part Number: UPN; alternate symbols: (C0402L); part number: CAP_SM-100PF,10V,20,E062219,C0402; tolerance: 20
C15 C48 C81 C114 C147 = CAP: Tolerance: 10; User Part Number: UPN; alternate symbols: (C0402L); part number: CAP_SM-0.01UF,25V,10,E030894,C0402; tolerance: 10
C16 C19 C49 C52 C82 C85 C115 C118 C148 C151 = CAP: Tolerance: 10; User Part Number: UPN; alternate symbols: (C0402L); part number: CAP_SM-1UF,16V,10,E019219,C0402; tolerance: 10
C18 C51 C84 C117 C150 = CAP: Tolerance: 10; User Part Number: UPN; alternate symbols: (C0603L); part number: CAP_SM-6800PF,50V,10,E007966,C0603; tolerance: 10
C21 C23 C54 C56 C87 C89 C120 C122 C153 C155 = CAP: Tolerance: 10; User Part Number: UPN; alternate symbols: (C0402L); part number: CAP_SM-4.7UF,10V,10,E028571,C0402; tolerance: 10
C24-C31 C57-C64 C90-C97 C123-C130 C156-C163 C196-C205 = CAP: User Part Number: UPN; Tolerance: 10; alternate symbols: (); part number: CAP_SM-10UF,100V,10,E067277,C1210H110; tolerance: 10
C32 C33 C65 C66 C98 C99 C131 C132 C164 C165 C178 C179 C182 C183 C186 C187 C190 C191 C194 C195 = CAPP: User Part Number: UPN; Tolerance: 20; alternate symbols: (); part number: CAPP_SM-47UF,80V,20,E067781,CPLSMSQ406H433; tolerance: 20
C166 = CAPP: Tolerance: 20; User Part Number: UPN; alternate symbols: (); part number: CAPP_SM-10UF,100V,20,E056094,CPLSMSQ260H315; tolerance: 20
C167 = CAP: User Part Number: UPN; Tolerance: 10; alternate symbols: (); part number: CAP_SM-1UF,100V,10,E042933,C1210H110; tolerance: 10
C168 = CAP: Tolerance: 10; User Part Number: UPN; alternate symbols: (); part number: CAP_SM-10UF,25V,10,E057469,C1206H71; tolerance: 10
C169 C170 C173 C174 = CAP: Tolerance: 10; User Part Number: UPN; alternate symbols: (C0402L); part number: CAP_SM-0.1UF,16V,10,E018707,C0402; tolerance: 10
C171 C172 = CAP: Tolerance: 10; User Part Number: UPN; alternate symbols: (C0603L); part number: CAP_SM-0.47UF,10V,10,E042657,C0603; tolerance: 10
C175 = CAP: Tolerance: 5; User Part Number: UPN; alternate symbols: (C0402L); part number: CAP_SM-1000PF,25V,5,E017843,C0402; tolerance: 5
D1-D10 = DIOSCHOTTKY: Tolerance: N/A; User Part Number: UPN; alternate symbols: (); part number: DIOSCHOTTKY_SM-BAT46WJ,115,100V,N/A,E016832,SOD323F; tolerance: N/A
J1-J8 = CNTP1P: Tolerance: N/A; User Part Number: UPN; alternate symbols: (CNCFCKFH1032-10_C450D200,CNCFCKFH1032-10_C380D200); part number: CNTP1P_TH-CKFH1032-10,E050511,CNCFCKFH1032-10; tolerance: N/A
JP1-JP4 = CN3P: User Part Number: UPN; Tolerance: N/A; alternate symbols: (); part number: CN3P_TH-TMM-103-02-L-S,E033760,CNTHMHDR1X3L236W78H215; tolerance: N/A
JP5 = CN8P_ODD_EVEN: User Part Number: UPN; Tolerance: N/A; alternate symbols: (); part number: CN8P_ODD_EVEN_TH-62000821121,E048747,CNTHMHDR2X4L315W157H248; tolerance: N/A
L1-L5 = IND: User Part Number: UPN; Tolerance: 15; alternate symbols: (); part number: IND_SM-10UH,15,E039085,LSML1102W764H728; tolerance: 15
M1-M40 = TRANNMOSFET_V15: Tolerance: N/A; User Part Number: UPN; alternate symbols: (); part number: TRANNMOSFET_V15_SM-ISC022N10NM6ATMA1,E067785,SON8_FL; tolerance: N/A
R1-R5 R9-R11 R13 R17 R22 R24 R28-R32 R34 R39-R41 R43 R47 R52 R54 R58-R62 R64 R75-R77 R79 R83 R88 R90 R95-R97 R99 R100 R102 R108-R110 R112 R116 R121 R123 R128-R130 R132 R133 R135 R141-R143 R145 R149 R154 R156 R161-R163 R165 R166 R168 R171-R186 = RES: Tolerance: JUMPER; User Part Number: UPN; alternate symbols: (R0402L,R0402L_ALT); part number: RES_SM-0,E003438,1/10W,JUMPER,R0402; tolerance: JUMPER
R6 R67 R69 R70 R73 R94 R106 R127 R139 R160 = RES: Tolerance: 5; User Part Number: UPN; alternate symbols: (R0402L); part number: RES_SM-1,E010031,1/10W,5,R0402; tolerance: 5
R7 R37 R72 R105 R138 = RES: Tolerance: 1; User Part Number: UPN; alternate symbols: (R0402L); part number: RES_SM-301K,E020913,1/10W,1,R0402; tolerance: 1
R8 R38 R74 R107 R140 = RES: Tolerance: 1; User Part Number: UPN; alternate symbols: (R0402L); part number: RES_SM-10.7K,E019637,1/16W,1,R0402; tolerance: 1
R12 R42 R78 R111 R144 = RES: Tolerance: 1; User Part Number: UPN; alternate symbols: (R0402L); part number: RES_SM-10K,E003751,1/10W,1,R0402; tolerance: 1
R14 R15 R44 R45 R80 R81 R113 R114 R146 R147 = RES: User Part Number: UPN; Tolerance: 1; alternate symbols: (); part number: RES_SM-0.003,E050854,3W,1,R1225H28; tolerance: 1
R16 R46 R82 R115 R148 = RES: Tolerance: 1; User Part Number: UPN; alternate symbols: (R0603L); part number: RES_SM-49.9,E003673,1/10W,1,R0603; tolerance: 1
R18 R48 R84 R117 R150 = RES: Tolerance: 1; User Part Number: UPN; alternate symbols: (R0402L); part number: RES_SM-69.8K,E019611,1/16W,1,R0402; tolerance: 1
R19-R21 R25 R26 R49-R51 R55 R56 R85-R87 R91 R92 R118-R120 R124 R125 R151-R153 R157 R158 = RES: User Part Number: UPN; alternate symbols: (R0402L,R0402L_ALT); part number: RES_SM-TBD0402,E004049,TBD0402,TBD0402,R0402
R23 R53 R89 R122 R155 = RES: User Part Number: UPN; alternate symbols: (R0603L); part number: RES_SM-TBD0603,E004050,TBD0603,TBD0603,R0603
R27 R57 R93 R126 R159 = RES: Tolerance: 1; User Part Number: UPN; alternate symbols: (R0402L,R0402L_ALT); part number: RES_SM-100K,E003796,1/10W,1,R0402; tolerance: 1
R33 R63 R101 R134 R167 R190-R194 = RES: User Part Number: UPN; Tolerance: N/A; alternate symbols: (); part number: RES_SM-0,E048848,2W,N/A,R1225H28; tolerance: N/A
R35 R65 R103 R136 R169 = RES: Tolerance: 1; User Part Number: UPN; alternate symbols: (R0402L); part number: RES_SM-475K,E050518,1/16W,1,R0402; tolerance: 1
R36 R66 R104 R137 R170 = RES: Tolerance: 1; User Part Number: UPN; alternate symbols: (R0402L,R0402L_ALT); part number: RES_SM-10K,E003751,1/10W,1,R0402; tolerance: 1
R68 R71 R98 R131 R164 = RES: Tolerance: 5; User Part Number: UPN; alternate symbols: (R0402L); part number: RES_SM-5.1,E017500,1/10W,5,R0402; tolerance: 5
R187 = RES: User Part Number: UPN; Tolerance: 1; alternate symbols: (R0805L); part number: RES_SM-267K,E003546,1/8W,1,R0805; tolerance: 1
R188 = RES: Tolerance: 1; User Part Number: UPN; alternate symbols: (R0402L); part number: RES_SM-3.9MEG,E030132,1/16W,1,R0402; tolerance: 1
R189 = RES: Tolerance: 1; User Part Number: UPN; alternate symbols: (R0402L); part number: RES_SM-2.21M,E047100,1/16W,1,R0402; tolerance: 1
TP1-TP8 TP22-TP25 TP30-TP33 TP56-TP59 TP73-TP76 = CNTP1P: User Part Number: UPN; Tolerance: N/A; alternate symbols: (); part number: CNTP1P_TH-2308-2-00-80-00-00-07-0,E030692,CNMILLMAX2308; tolerance: N/A
TP9-TP21 TP26-TP29 TP34-TP55 TP60-TP72 TP77-TP89 = NCTESTPAD: Tolerance: N/A; User Part Number: UPN; alternate symbols: (); part number: NCTESTPAD_SM-TESTPAD,E019801,TPSMC40; tolerance: N/A
U1-U5 = ADLTC7878_V2: Tolerance: N/A; User Part Number: UPN; alternate symbols: (); part number: ADLTC7878_V2_SM-LTC7878AUK#PBF,E065407,QFN48_7X7_PAD4_7X4_7_A; tolerance: N/A
U6 = ADLT3014_V2: User Part Number: UPN; Tolerance: N/A; alternate symbols: (); part number: ADLT3014_V2_SM-LT3014ES5#TRPBF,E065501,TSOT-5; tolerance: N/A
U7 = ADLTC6909: Tolerance: N/A; User Part Number: UPN; alternate symbols: (); part number: ADLTC6909_SM-LTC6909CMS#PBF,E035296,MSOP16; tolerance: N/A

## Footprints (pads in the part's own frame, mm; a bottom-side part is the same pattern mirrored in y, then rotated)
C0402
  rect 0.635x0.508 smd: 1(-0.564,0) 2(0.564,0)
C0603
  rect 0.762x0.762 smd: 1(-0.813,0) 2(0.813,0)
C0805H55
  rect 1.143x1.448 smd: 1(-0.9,0) 2(0.9,0)
C1206H71
  rect 1.6x2.007 smd: 1(-1.397,0) 2(1.397,0)
C1210H87
  rect 1.092x2.464 smd: 1(-1.646,0) 2(1.646,0)
C1210H110
  rect 1.372x2.794 smd: 1(-1.431,0) 2(1.431,0)
CNCFCKFH1032-10
  round 9.906 hole 5.08: 1(0,0)
CNMILLMAX2308
  round 2.286 hole 1.778: 1(0,0)
CNTHMHDR1X3L236W78H215
  rect 1.524x1.524 hole 1.016: 1(0,0)
  round 1.524 hole 1.016: 2(2,0) 3(4,0)
CNTHMHDR2X4L315W157H248
  rect 1.397x1.397 hole 0.889: 1(0,0)
  round 1.397 hole 0.889: 2(0,2) 3(2,0) 4(2,2) 5(4,0) 6(4,2) 7(6,0) 8(6,2)
CPLSMSQ260H315
  rect 3.099x1.651 smd: N(2.85,0) P(-2.85,0)
CPLSMSQ406H413
  rect 4.293x2.108 smd: N(4.45,0) P(-4.45,0)
CPLSMSQ406H433
  rect 4.064x2.159 smd: N(4.187,0) P(-4.187,0)
LSML1102W764H728
  rect 6.35x5.283 smd: (0,10.514)
  rect 5.334x5.588 smd: 1(-5.075,-11.56) 2(5.075,-11.56)
MSOP16
  rect 0.305x1.397 smd: 1(-1.75,-2.2) 2(-1.25,-2.2) 3(-0.75,-2.2) 4(-0.25,-2.2) 5(0.25,-2.2) 6(0.75,-2.2) 7(1.25,-2.2) 8(1.75,-2.2) 9(1.75,2.2) 10(1.25,2.2) 11(0.75,2.2) 12(0.25,2.2) 13(-0.25,2.2) 14(-0.75,2.2) 15(-1.25,2.2) 16(-1.75,2.2)
QFN48_7X7_PAD4_7X4_7_A
  oval 0.305x0.889 smd: 1(-2.75,-3.45) 2(-2.25,-3.45) 3(-1.75,-3.45) 4(-1.25,-3.45) 5(-0.75,-3.45) 6(-0.25,-3.45) 7(0.25,-3.45) 8(0.75,-3.45) 9(1.25,-3.45) 10(1.75,-3.45) 11(2.25,-3.45) 12(2.75,-3.45) 25(2.75,3.45) 26(2.25,3.45) 27(1.75,3.45) 28(1.25,3.45) 29(0.75,3.45) 30(0.25,3.45) 31(-0.25,3.45) 32(-0.75,3.45) 33(-1.25,3.45) 34(-1.75,3.45) 35(-2.25,3.45) 36(-2.75,3.45)
  oval 0.889x0.305 smd: 13(3.45,-2.75) 14(3.45,-2.25) 15(3.45,-1.75) 16(3.45,-1.25) 17(3.45,-0.75) 18(3.45,-0.25) 19(3.45,0.25) 20(3.45,0.75) 21(3.45,1.25) 22(3.45,1.75) 23(3.45,2.25) 24(3.45,2.75) 37(-3.45,2.75) 38(-3.45,2.25) 39(-3.45,1.75) 40(-3.45,1.25) 41(-3.45,0.75) 42(-3.45,0.25) 43(-3.45,-0.25) 44(-3.45,-0.75) 45(-3.45,-1.25) 46(-3.45,-1.75) 47(-3.45,-2.25) 48(-3.45,-2.75)
  rect 4.699x4.699 smd: 49(0,0)
R0402
  rect 0.635x0.508 smd: 1(-0.564,0) 2(0.564,0)
R0603
  rect 0.762x0.762 smd: 1(-0.813,0) 2(0.813,0)
R0805
  rect 1.041x1.397 smd: 1(-0.95,0) 2(0.95,0)
R1225H28
  rect 0.991x6.579 smd: 1(-1.595,0) 2(1.595,0)
SOD323F
  rect 0.838x0.457 smd: A(1.14,0) C(-1.14,0)
SON8_FL
  round 0.127 smd: 1(-1.905,-3.071) 2(-0.635,-3.071) 6(0.635,2.931) 7(-0.635,2.931) 8(-1.905,2.931)
  custom 0.273x0.273 smd: 3(0.635,-3.071)
  rect 0.508x1.092 smd: 4(1.905,-2.779)
  custom 1.105x1.105 smd: 5(1.905,2.931)
TPSMC40
  round 1.143 smd: 1(0,0)
TSOT-5
  rect 0.508x1.524 smd: 1(-0.95,-1.17) 2(0,-1.17) 3(0.95,-1.17) 4(0.95,1.17) 5(-0.95,1.17)
unnamed#2
  round 4.75 hole 4.75 unplated: (0,0)

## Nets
SGND: C11.2(N2) C13.2(N2) C14.2(N2) C15.2(N2) C21.2(N2) C44.2(N2) C46.2(N2) C47.2(N2) C48.2(N2) C54.2(N2) C77.2(N2) C79.2(N2) C80.2(N2) C81.2(N2) C87.2(N2) C110.2(N2) C112.2(N2) C113.2(N2) C114.2(N2) C120.2(N2) C143.2(N2) C145.2(N2) C146.2(N2) C147.2(N2) C153.2(N2) R8.1 R18.2(N2) R20.2(N2) R22.2(N2) R24.2(N2) R36.2(N2) R38.1 R48.2(N2) R50.2(N2) R52.2(N2) R54.2(N2) R66.2(N2) R74.1 R84.2(N2) R86.2(N2) R88.2(N2) R90.2(N2) R104.2(N2) R107.1 R117.2(N2) R119.2(N2) R121.2(N2) R123.2(N2) R137.2(N2) R140.1 R150.2(N2) R152.2(N2) R154.2(N2) R156.2(N2) R170.2(N2) TP3.1(N1) TP6.1(N1) TP21.1(N1) TP31.1(N1) TP46.1(N1) TP55.1(N1) TP57.1(N1) TP72.1(N1) TP74.1(N1) TP89.1(N1) U1.49 U2.49 U3.49 U4.49 U5.49
VIN: C1.P C2.P C3.1 C4.1 C5.1 C6.1 C7.1 C8.1 C9.1 C10.1 C34.P C35.P C36.1 C37.1 C38.1 C39.1 C40.1 C41.1 C42.1 C43.1 C67.P C68.P C69.1 C70.1 C71.1 C72.1 C73.1 C74.1 C75.1 C76.1 C100.P C101.P C102.1 C103.1 C104.1 C105.1 C106.1 C107.1 C108.1 C109.1 C133.P C134.P C135.1 C136.1 C137.1 C138.1 C139.1 C140.1 C141.1 C142.1 C166.P C167.1 C176.P C177.P C180.P C181.P C184.P C185.P C188.P C189.P C192.P C193.P C206.P C207.P C210.P C211.P C214.P C215.P C218.P C219.P C222.P C223.P J1.1(N1) J5.1(N1) JP4.1 M1.5 M1.6 M1.7 M1.8 M5.5 M5.6 M5.7 M5.8 M9.5 M9.6 M9.7 M9.8 M13.5 M13.6 M13.7 M13.8 M17.5 M17.6 M17.7 M17.8 M21.5 M21.6 M21.7 M21.8 M25.5 M25.6 M25.7 M25.8 M29.5 M29.6 M29.7 M29.8 M33.5 M33.6 M33.7 M33.8 M37.5 M37.6 M37.7 M37.8 R6.1 R7.1 R37.1 R69.1 R72.1 R73.1 R105.1 R106.1 R138.1 R139.1 TP1.1(N1) U6.1
CLKOUT_1: TP8.1(N1) U1.29
CLKOUT_2: TP33.1(N1) U2.29
CLKOUT_3: TP24.1(N1) U3.29
CLKOUT_4: TP59.1(N1) U4.29
CLKOUT_5: TP76.1(N1) U5.29
DRVCC_1: C23.1 D1.A(P) D2.A(P) TP17.1(N1) U1.7
DRVCC_2: C56.1 D3.A(P) D4.A(P) TP42.1(N1) U2.7
DRVCC_3: C89.1 D5.A(P) D6.A(P) TP51.1(N1) U3.7
DRVCC_4: C122.1 D7.A(P) D8.A(P) TP68.1(N1) U4.7
DRVCC_5: C155.1 D9.A(P) D10.A(P) TP85.1(N1) U5.7
GROUND: C1.N(N2) C2.N(N2) C3.2(N2) C4.2(N2) C5.2(N2) C6.2(N2) C7.2(N2) C8.2(N2) C9.2(N2) C10.2(N2) C12.2(N2) C20.2(N2) C23.2(N2) C24.2(N2) C25.2(N2) C26.2(N2) C27.2(N2) C28.2(N2) C29.2(N2) C30.2(N2) C31.2(N2) C32.N(N2) C33.N(N2) C34.N(N2) C35.N(N2) C36.2(N2) C37.2(N2) C38.2(N2) C39.2(N2) C40.2(N2) C41.2(N2) C42.2(N2) C43.2(N2) C45.2(N2) C53.2(N2) C56.2(N2) C57.2(N2) C58.2(N2) C59.2(N2) C60.2(N2) C61.2(N2) C62.2(N2) C63.2(N2) C64.2(N2) C65.N(N2) C66.N(N2) C67.N(N2) C68.N(N2) C69.2(N2) C70.2(N2) C71.2(N2) C72.2(N2) C73.2(N2) C74.2(N2) C75.2(N2) C76.2(N2) C78.2(N2) C86.2(N2) C89.2(N2) C90.2(N2) C91.2(N2) C92.2(N2) C93.2(N2) C94.2(N2) C95.2(N2) C96.2(N2) C97.2(N2) C98.N(N2) C99.N(N2) C100.N(N2) C101.N(N2) C102.2(N2) C103.2(N2) C104.2(N2) C105.2(N2) C106.2(N2) C107.2(N2) C108.2(N2) C109.2(N2) C111.2(N2) C119.2(N2) C122.2(N2) C123.2(N2) C124.2(N2) C125.2(N2) C126.2(N2) C127.2(N2) C128.2(N2) C129.2(N2) C130.2(N2) C131.N(N2) C132.N(N2) C133.N(N2) C134.N(N2) C135.2(N2) C136.2(N2) C137.2(N2) C138.2(N2) C139.2(N2) C140.2(N2) C141.2(N2) C142.2(N2) C144.2(N2) C152.2(N2) C155.2(N2) C156.2(N2) C157.2(N2) C158.2(N2) C159.2(N2) C160.2(N2) C161.2(N2) C162.2(N2) C163.2(N2) C164.N(N2) C165.N(N2) C166.N(N2) C167.2(N2) C168.1 C169.1 C170.1 C171.2(N2) C172.2(N2) C173.2(N2) C174.2(N2) C175.2(N2) C176.N(N2) C177.N(N2) C178.N(N2) C179.N(N2) C180.N(N2) C181.N(N2) C182.N(N2) C183.N(N2) C184.N(N2) C185.N(N2) C186.N(N2) C187.N(N2) C188.N(N2) C189.N(N2) C190.N(N2) C191.N(N2) C192.N(N2) C193.N(N2) C194.N(N2) C195.N(N2) C196.2(N2) C197.2(N2) C198.2(N2) C199.2(N2) C200.2(N2) C201.2(N2) C202.2(N2) C203.2(N2) C204.2(N2) C205.2(N2) C206.N(N2) C207.N(N2) C208.N(N2) C209.N(N2) C210.N(N2) C211.N(N2) C212.N(N2) C213.N(N2) C214.N(N2) C215.N(N2) C216.N(N2) C217.N(N2) C218.N(N2) C219.N(N2) C220.N(N2) C221.N(N2) C222.N(N2) C223.N(N2) C224.N(N2) C225.N(N2) J2.1(N1) J4.1(N1) J6.1(N1) J8.1(N1) JP1.3(N3) JP2.3(N3) JP3.3(N3) JP4.3(N3) JP5.6 M2.1 M2.2 M2.3(S3) M3.1 M3.2 M3.3(S3) M6.1 M6.2 M6.3(S3) M7.1 M7.2 M7.3(S3) M10.1 M10.2 M10.3(S3) M11.1 M11.2 M11.3(S3) M14.1 M14.2 M14.3(S3) M15.1 M15.2 M15.3(S3) M18.1 M18.2 M18.3(S3) M19.1 M19.2 M19.3(S3) M22.1 M22.2 M22.3(S3) M23.1 M23.2 M23.3(S3) M26.1 M26.2 M26.3(S3) M27.1 M27.2 M27.3(S3) M30.1 M30.2 M30.3(S3) M31.1 M31.2 M31.3(S3) M34.1 M34.2 M34.3(S3) M35.1 M35.2 M35.3(S3) M38.1 M38.2 M38.3(S3) M39.1 M39.2 M39.3(S3) R189.2(N2) TP4.1(N1) TP25.1(N1) U1.11 U2.11 U3.11 U4.11 U5.11 U6.2 U7.2
INTVCC_1: C21.1 R25.2(N2) R26.2(N2) R27.2(N2) TP14.1(N1) U1.9
INTVCC_2: C54.1 R55.2(N2) R56.2(N2) R57.2(N2) TP39.1(N1) U2.9
INTVCC_3: C87.1 R91.2(N2) R92.2(N2) R93.2(N2) TP48.1(N1) U3.9
INTVCC_4: C120.1 R124.2(N2) R125.2(N2) R126.2(N2) TP65.1(N1) U4.9
INTVCC_5: C153.1 R157.2(N2) R158.2(N2) R159.2(N2) TP82.1(N1) U5.9
ITH_1: C14.1 R4.1 R11.1 R12.1 TP10.1(N1) U1.22
ITH_2: C47.1 R4.2(N2) R41.1 R42.1 R174.1 TP35.1(N1) U2.22
ITH_3: C80.1 R77.1 R78.1 R174.2(N2) R179.1 TP27.1(N1) U3.22
ITH_4: C113.1 R110.1 R111.1 R179.2(N2) R184.1 TP61.1(N1) U4.22
ITH_5: C146.1 R143.1 R144.1 R184.2(N2) TP78.1(N1) U5.22
OUT1: JP5.8(N8) R1.1 U7.5
OUT2: R171.1 U7.6
OUT3: R176.1 U7.7
OUT4: R181.1 U7.8
OUT5: R186.1 U7.9
RUN_1: C13.1 R2.1 R7.2(N2) R8.2(N2) TP5.1(N1) U1.10
RUN_2: C46.1 R2.2(N2) R37.2(N2) R38.2(N2) R172.1 TP30.1(N1) U2.10
RUN_3: C79.1 R72.2(N2) R74.2(N2) R172.2(N2) R177.1 TP2.1(N1) U3.10
RUN_4: C112.1 R105.2(N2) R107.2(N2) R177.2(N2) R182.1 TP56.1(N1) U4.10
RUN_5: C145.1 R138.2(N2) R140.2(N2) R182.2(N2) TP73.1(N1) U5.10
SS_1: C11.1 R3.1 TP9.1(N1) U1.20
SS_2: C44.1 R3.2(N2) R173.1 TP34.1(N1) U2.20
SS_3: C77.1 R173.2(N2) R178.1 TP26.1(N1) U3.20
SS_4: C110.1 R178.2(N2) R183.1 TP60.1(N1) U4.20
SS_5: C143.1 R183.2(N2) TP77.1(N1) U5.20
SYNC_1: R1.2(N2) TP7.1(N1) U1.30
SYNC_2: R171.2(N2) TP32.1(N1) U2.30
SYNC_3: R176.2(N2) TP23.1(N1) U3.30
SYNC_4: R181.2(N2) TP58.1(N1) U4.30
SYNC_5: R186.2(N2) TP75.1(N1) U5.30
UNNAMED_1_ADLTC7878V2_I139_BG1: R10.2(N2) U1.1
UNNAMED_1_ADLTC7878V2_I139_BG2: R28.2(N2) U1.12
UNNAMED_1_ADLTC7878V2_I139_BOOST1: C16.1 D1.C U1.46
UNNAMED_1_ADLTC7878V2_I139_BOOST2: C19.2(N2) D2.C U1.15
UNNAMED_1_ADLTC7878V2_I139_CSN: R29.1 TP11.1(N1) U1.35
UNNAMED_1_ADLTC7878V2_I139_CSP: C22.1 R31.1 TP16.1(N1) U1.34
UNNAMED_1_ADLTC7878V2_I139_EXTVCC: C20.1 R70.1 TP12.1(N1) U1.8
UNNAMED_1_ADLTC7878V2_I139_FREQ: R18.1 U1.28
UNNAMED_1_ADLTC7878V2_I139_ISNSD: C17.1 R17.1 R21.1 U1.43
UNNAMED_1_ADLTC7878V2_I139_ISNSN: C18.2(N2) R16.2(N2) R21.2(N2) R23.2(N2) U1.41
UNNAMED_1_ADLTC7878V2_I139_ISNSP: C17.2(N2) C18.1 R13.2(N2) R17.2(N2) R19.2(N2) U1.42
UNNAMED_1_ADLTC7878V2_I139_ITHB: R11.2(N2) U1.21
UNNAMED_1_ADLTC7878V2_I139_MODE: R22.1 R26.1 U1.26
UNNAMED_1_ADLTC7878V2_I139_PGOOD: R27.1 TP15.1(N1) U1.19
UNNAMED_1_ADLTC7878V2_I139_PHASMD: R24.1 R25.1 U1.27
UNNAMED_1_ADLTC7878V2_I139_SETCUR: R20.1 U1.31
UNNAMED_1_ADLTC7878V2_I139_SW1: C16.2(N2) M1.1 M1.2 M1.3(S3) M2.5 M2.6 M2.7 M2.8 M5.1 M5.2 M5.3(S3) M6.5 M6.6 M6.7 M6.8 R13.1 R14.1 R15.1 U1.45
UNNAMED_1_ADLTC7878V2_I139_SW2: C19.1 L1.2(N2) M3.5 M3.6 M3.7 M3.8 M4.1 M4.2 M4.3(S3) M7.5 M7.6 M7.7 M7.8 M8.1 M8.2 M8.3(S3) R23.1 U1.16
UNNAMED_1_ADLTC7878V2_I139_TG1: R9.2(N2) U1.47
UNNAMED_1_ADLTC7878V2_I139_TG2: R30.2(N2) U1.14
UNNAMED_1_ADLTC7878V2_I139_VIN: C12.1 R69.2(N2) U1.4
UNNAMED_1_ADLTC7878V2_I139_VOUT: R70.2(N2) R71.1 U1.38(VOUT)
UNNAMED_1_CAP_I38_N1: C15.1 R12.2(N2)
UNNAMED_1_CAP_I100_N2: C22.2(N2) R29.2(N2) R32.1 TP13.1(N1)
UNNAMED_1_IND_I92_N1: L1.1 R14.2(N2) R15.2(N2) R16.1 R19.1
UNNAMED_1_NCTESTPAD_I113_N1: R34.2(N2) R35.1 TP20.1(N1)
UNNAMED_1_RES_I72_N1: M1.4 M5.4 R9.1
UNNAMED_1_RES_I73_N1: M2.4 M6.4 R10.1
UNNAMED_1_RES_I87_N1: M3.4 M7.4 R28.1
UNNAMED_1_RES_I115_N1: M4.4 M8.4 R30.1
UNNAMED_2_ADLTC7878V2_I124_BG1: R40.2(N2) U2.1
UNNAMED_2_ADLTC7878V2_I124_BG2: R58.2(N2) U2.12
UNNAMED_2_ADLTC7878V2_I124_BOOST1: C49.1 D3.C U2.46
UNNAMED_2_ADLTC7878V2_I124_BOOST2: C52.2(N2) D4.C U2.15
UNNAMED_2_ADLTC7878V2_I124_CSN: R59.1 TP36.1(N1) U2.35
UNNAMED_2_ADLTC7878V2_I124_CSP: C55.1 R61.1 TP41.1(N1) U2.34
UNNAMED_2_ADLTC7878V2_I124_EXTVCC: C53.1 R67.1 TP37.1(N1) U2.8
UNNAMED_2_ADLTC7878V2_I124_FREQ: R48.1 U2.28
UNNAMED_2_ADLTC7878V2_I124_ISNSD: C50.1 R47.1 R51.1 U2.43
UNNAMED_2_ADLTC7878V2_I124_ISNSN: C51.2(N2) R46.2(N2) R51.2(N2) R53.2(N2) U2.41
UNNAMED_2_ADLTC7878V2_I124_ISNSP: C50.2(N2) C51.1 R43.2(N2) R47.2(N2) R49.2(N2) U2.42
UNNAMED_2_ADLTC7878V2_I124_ITHB: R41.2(N2) U2.21
UNNAMED_2_ADLTC7878V2_I124_MODE: R52.1 R56.1 U2.26
UNNAMED_2_ADLTC7878V2_I124_PGOOD: R57.1 TP40.1(N1) U2.19
UNNAMED_2_ADLTC7878V2_I124_PHASMD: R54.1 R55.1 U2.27
UNNAMED_2_ADLTC7878V2_I124_SETCUR: R50.1 U2.31
UNNAMED_2_ADLTC7878V2_I124_SW1: C49.2(N2) M9.1 M9.2 M9.3(S3) M10.5 M10.6 M10.7 M10.8 M13.1 M13.2 M13.3(S3) M14.5 M14.6 M14.7 M14.8 R43.1 R44.1 R45.1 U2.45
UNNAMED_2_ADLTC7878V2_I124_SW2: C52.1 L2.2(N2) M11.5 M11.6 M11.7 M11.8 M12.1 M12.2 M12.3(S3) M15.5 M15.6 M15.7 M15.8 M16.1 M16.2 M16.3(S3) R53.1 U2.16
UNNAMED_2_ADLTC7878V2_I124_TG1: R39.2(N2) U2.47
UNNAMED_2_ADLTC7878V2_I124_TG2: R60.2(N2) U2.14
UNNAMED_2_ADLTC7878V2_I124_VIN: C45.1 R6.2(N2) U2.4
UNNAMED_2_ADLTC7878V2_I124_VOUT: R67.2(N2) R68.1 U2.38(VOUT)
UNNAMED_2_CAP_I32_N1: C48.1 R42.2(N2)
UNNAMED_2_CAP_I92_N2: C55.2(N2) R59.2(N2) R62.1 TP38.1(N1)
UNNAMED_2_IND_I83_N1: L2.1 R44.2(N2) R45.2(N2) R46.1 R49.1
UNNAMED_2_NCTESTPAD_I104_N1: R64.2(N2) R65.1 TP45.1(N1)
UNNAMED_2_RES_I63_N1: M9.4 M13.4 R39.1
UNNAMED_2_RES_I64_N1: M10.4 M14.4 R40.1
UNNAMED_2_RES_I78_N1: M11.4 M15.4 R58.1
UNNAMED_2_RES_I106_N1: M12.4 M16.4 R60.1
UNNAMED_3_ADLTC7878V2_I47_BG1: R76.2(N2) U3.1
UNNAMED_3_ADLTC7878V2_I47_BG2: R95.2(N2) U3.12
UNNAMED_3_ADLTC7878V2_I47_BOOST1: C82.1 D5.C U3.46
UNNAMED_3_ADLTC7878V2_I47_BOOST2: C85.2(N2) D6.C U3.15
UNNAMED_3_ADLTC7878V2_I47_CSN: R96.1 TP28.1(N1) U3.35
UNNAMED_3_ADLTC7878V2_I47_CSP: C88.1 R99.1 TP50.1(N1) U3.34
UNNAMED_3_ADLTC7878V2_I47_EXTVCC: C86.1 R94.1 TP29.1(N1) U3.8
UNNAMED_3_ADLTC7878V2_I47_FREQ: R84.1 U3.28
UNNAMED_3_ADLTC7878V2_I47_ISNSD: C83.1 R83.1 R87.1 U3.43
UNNAMED_3_ADLTC7878V2_I47_ISNSN: C84.2(N2) R82.2(N2) R87.2(N2) R89.2(N2) U3.41
UNNAMED_3_ADLTC7878V2_I47_ISNSP: C83.2(N2) C84.1 R79.2(N2) R83.2(N2) R85.2(N2) U3.42
UNNAMED_3_ADLTC7878V2_I47_ITHB: R77.2(N2) U3.21
UNNAMED_3_ADLTC7878V2_I47_MODE: R88.1 R92.1 U3.26
UNNAMED_3_ADLTC7878V2_I47_PGOOD: R93.1 TP49.1(N1) U3.19
UNNAMED_3_ADLTC7878V2_I47_PHASMD: R90.1 R91.1 U3.27
UNNAMED_3_ADLTC7878V2_I47_SETCUR: R86.1 U3.31
